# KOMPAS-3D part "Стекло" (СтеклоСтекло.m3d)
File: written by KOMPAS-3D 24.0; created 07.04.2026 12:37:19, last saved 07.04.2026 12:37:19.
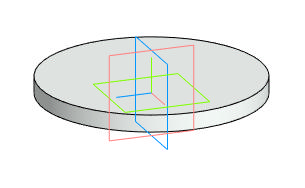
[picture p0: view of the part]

Document properties: Автор: Main; Полное имя файла: D:\DN.ru Аутсерс\Стекло смотровое DN.ru\Исходники\Стекло смотровое DN.ru SG2-34G-F тип В ГОСТ 21836-2021 Ду100 Ру16, углеродистая сталь, фланцевое\СтеклоСтекло.m3d

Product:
- Body: Твердое тело1  | qty 1
- Part/product: Стекло

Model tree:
1. Твердое тело1  (labels: Твердое тело1)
